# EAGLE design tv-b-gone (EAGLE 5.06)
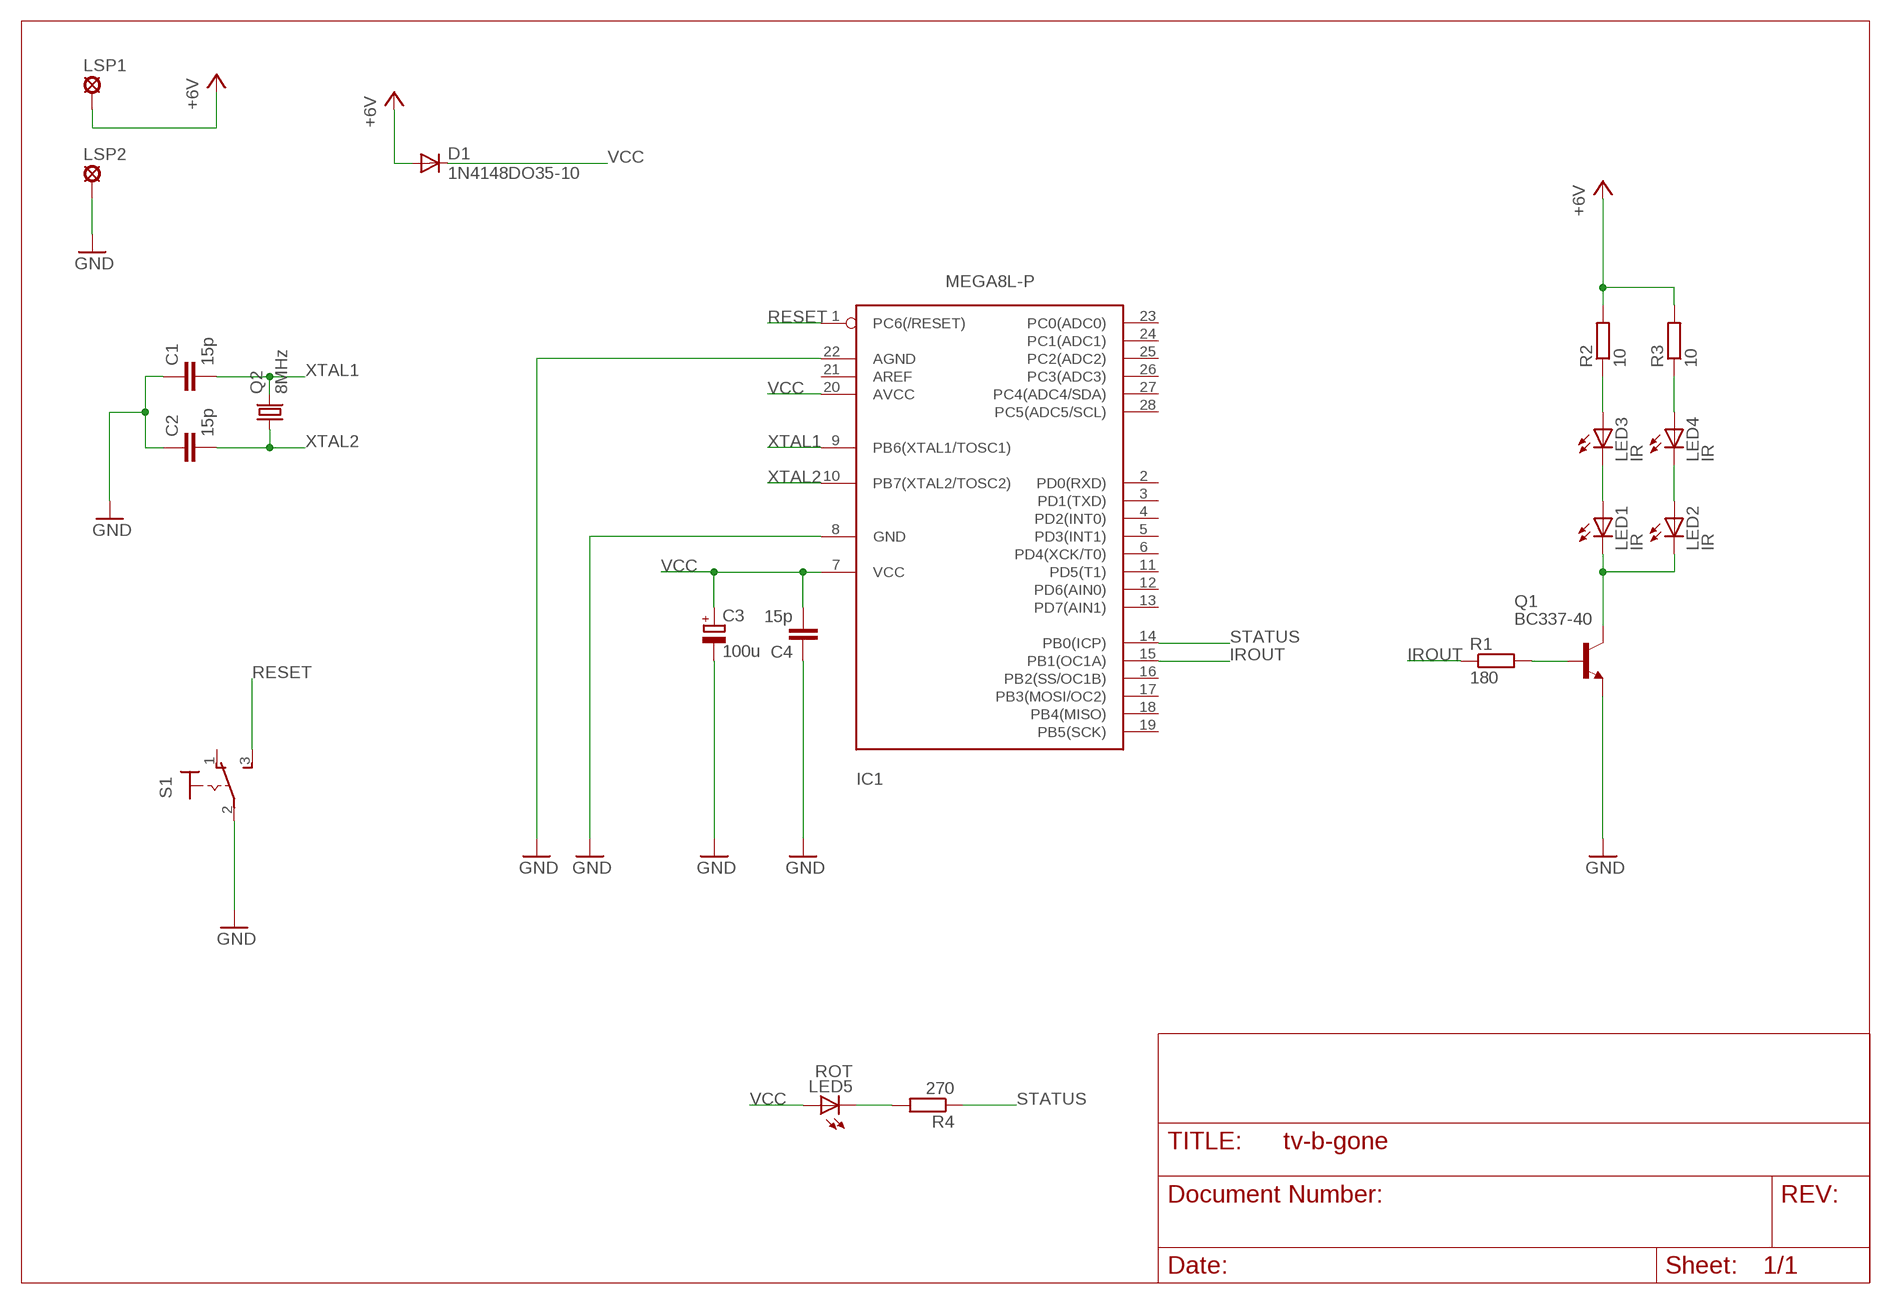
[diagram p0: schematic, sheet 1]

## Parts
C1  15p  C-EU025-030X050  [C025-030X050]
C2  15p  C-EU025-030X050  [C025-030X050]
C3  100u  CPOL-EUE2.5-5  [E2,5-5]
C4  15p  C-EU025-030X050  [C025-030X050]
D1  1N4148DO35-10  [DO35-10]
IC1  MEGA8L-P  MEGA8-P  [DIL28-3]
LED1  IR  LED5MM  [LED5MM]
LED2  IR  LED5MM  [LED5MM]
LED3  IR  LED5MM  [LED5MM]
LED4  IR  LED5MM  [LED5MM]
LED5  ROT  LED5MM  [LED5MM]
LSP1  SE14  [SE14]
LSP2  SE14  [SE14]
Q1  BC337-40  BC337  [TO92]
Q2  8MHz  CRYSTALHC49S  [HC49/S]
R1  180  R-EU_0309/12  [0309/12]
R2  10  R-EU_0309/12  [0309/12]
R3  10  R-EU_0309/12  [0309/12]
R4  270  R-EU_0309/12  [0309/12]
S1  M9040P  [M9040P]

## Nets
+5V: D1.A LSP1.MP R2.2 R3.2 ; supply symbol labelled +6V
GND: C1.1 C2.1 C3.- C4.1 IC1.8(GND) IC1.22(AGND) LSP2.MP Q1.1(E) S1.2(P)
IR-N$5: LED2.A LED4.K(C)
IROUT: IC1.15(PB1(OC1A)) R1.1
N$2: Q1.2(B) R1.2
N$3: LED1.K(C) LED2.K(C) Q1.3(C)
N$4: LED1.A LED3.K(C)
N$6: LED3.A R2.1
N$7: LED4.A R3.1
N$8: LED5.K(C) R4.2
RESET: IC1.1(PC6(/RESET)) S1.3(S)
STATUS: IC1.14(PB0(ICP)) R4.1
VCC: C3.+ C4.2 D1.C IC1.7(VCC) IC1.20(AVCC) LED5.A
XTAL1: C1.2 IC1.9(PB6(XTAL1/TOSC1)) Q2.2
XTAL2: C2.2 IC1.10(PB7(XTAL2/TOSC2)) Q2.1
Unconnected: IC1.2(PD0(RXD)) IC1.3(PD1(TXD)) IC1.4(PD2(INT0)) IC1.5(PD3(INT1)) IC1.6(PD4(XCK/T0)) IC1.11(PD5(T1)) IC1.12(PD6(AIN0)) IC1.13(PD7(AIN1)) IC1.16(PB2(SS/OC1B)) IC1.17(PB3(MOSI/OC2)) IC1.18(PB4(MISO)) IC1.19(PB5(SCK)) IC1.21(AREF) IC1.23(PC0(ADC0)) IC1.24(PC1(ADC1)) IC1.25(PC2(ADC2)) IC1.26(PC3(ADC3)) IC1.27(PC4(ADC4/SDA)) IC1.28(PC5(ADC5/SCL)) S1.1(O)

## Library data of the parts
C1 C2 C4 = rcl:C-EU: CAPACITOR, European symbol
C3 = rcl:CPOL-EU: POLARIZED CAPACITOR, European symbol
D1 = diode:1N4148: DIODE
IC1 = avr:MEGA8-P: MICROCONTROLLER 8 Kbytes FLASH 1 kbytes SRAM 512 bytes EEPROM USART 4-channel 10 bit ADC 2-channel 8 bit ADC
LED1-LED5 = led:LED: LED
LSP1 LSP2 = solpad:SE14: SOLDER PAD
Q1 = transistor-npn:BC337*: NPN Transistor
Q2 = crystal:CRYSTAL: CRYSTAL
R1-R4 = rcl:R-EU_: RESISTOR, European symbol
S1 = switch:M9040P: TOGGLE SWITCH Marquardt

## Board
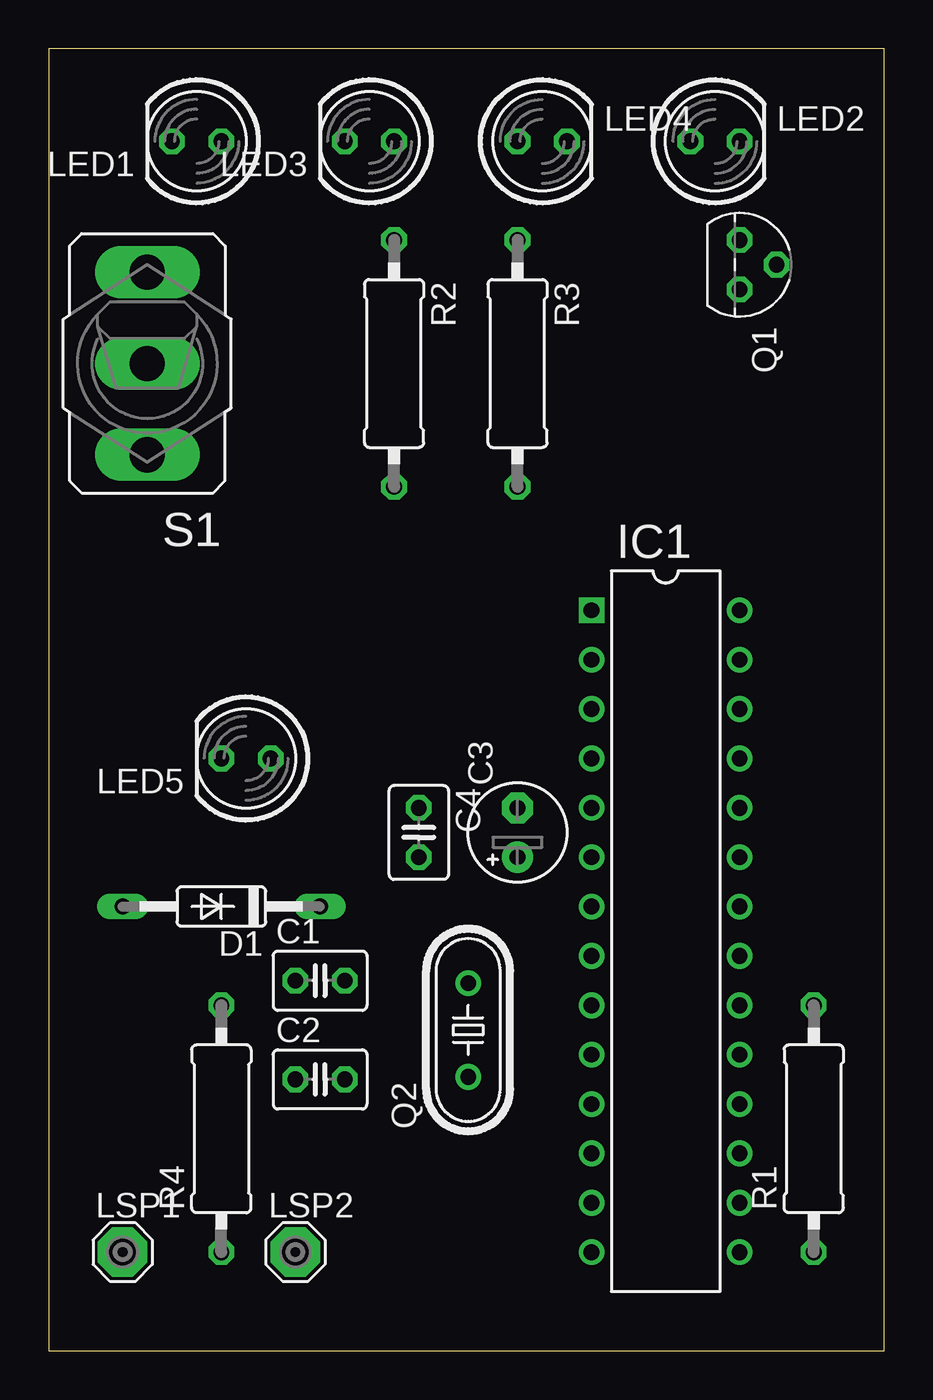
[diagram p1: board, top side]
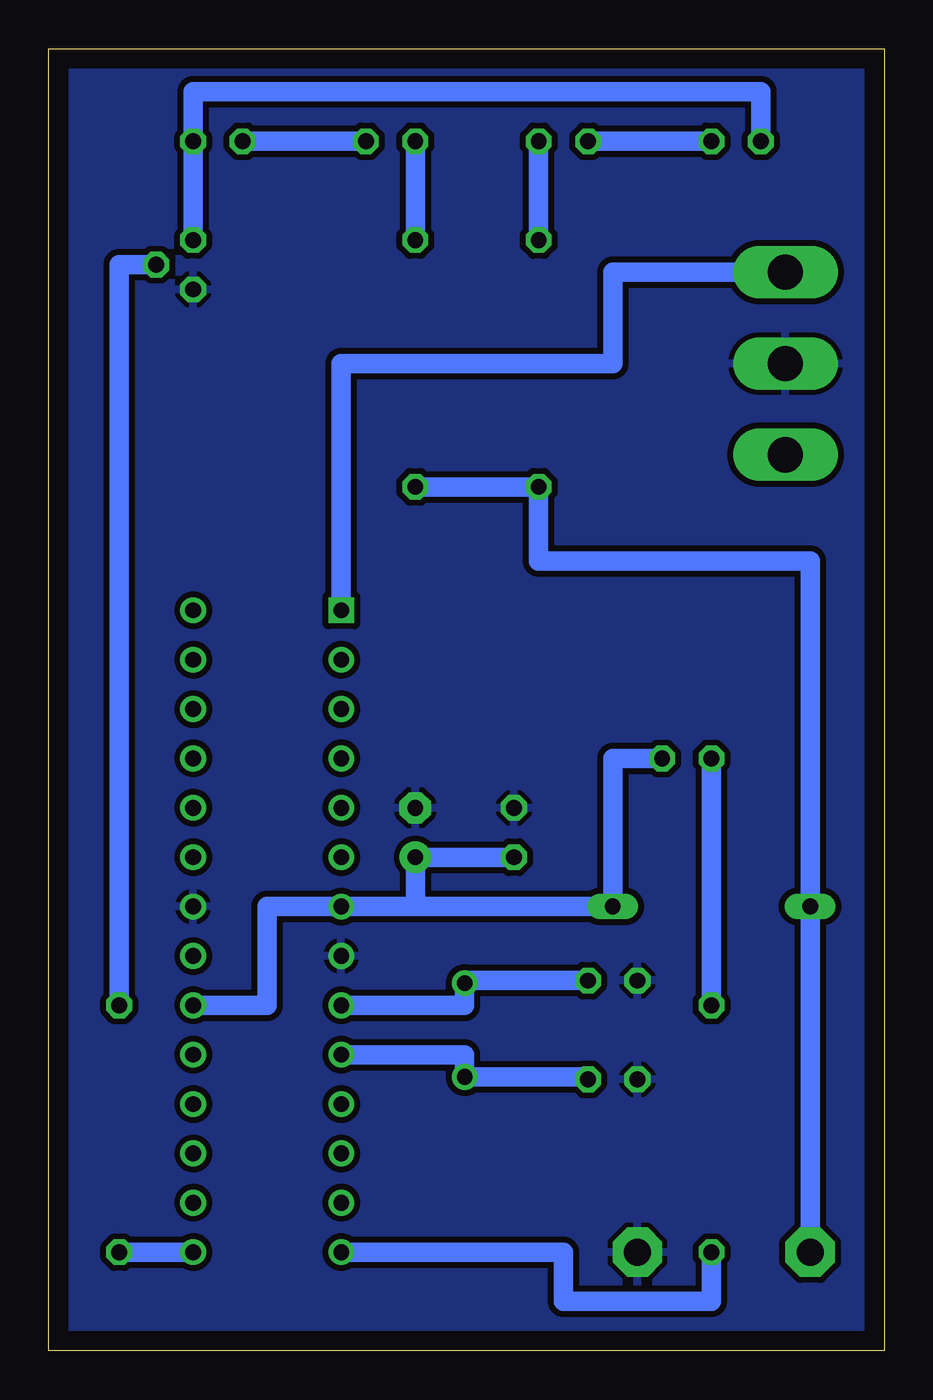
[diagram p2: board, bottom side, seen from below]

Size 43 x 67 mm. Coordinates in mm from the lower left corner, seen from the top.
Outline: 0,0 43,0 43,67 0,67 0,0
Copper layers (1*16): Top 0.035mm / dielectric 1.5mm / Bottom 0.035mm
Design rules "default *": minimum track width 10mil, minimum drill 24mil, track to track 12mil, track to pad 12mil, pad to pad 8mil, via to via 8mil, smd to smd 8mil, copper to edge 40mil, drill to drill 8mil, minimum pad ring 10mil, minimum via ring 8mil, stop-mask expansion 4mil, vias tented up to drill 0mil, thermal gap 10mil

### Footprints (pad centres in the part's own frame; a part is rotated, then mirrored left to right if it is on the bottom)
C025-030X050 = drill 0.813 octagon: 1 -1.27,0; 2 1.27,0
E2,5-5 = drill 0.813 pad 1.6 round: + -1.27,0 | drill 0.813 pad 1.6 octagon: - 1.27,0
DO35-10 = drill 0.813 long: A 5.08,0; C -5.08,0
DIL28-3 = drill 0.813 square: 1 -16.51,-3.81 | drill 0.813 round: 2 -13.97,-3.81; 3 -11.43,-3.81; 4 -8.89,-3.81; 5 -6.35,-3.81; 6 -3.81,-3.81; 7 -1.27,-3.81; 8 1.27,-3.81; 9 3.81,-3.81; 10 6.35,-3.81; 11 8.89,-3.81; 12 11.43,-3.81; 13 13.97,-3.81; 14 16.51,-3.81; 15 16.51,3.81; 16 13.97,3.81; 17 11.43,3.81; 18 8.89,3.81; 19 6.35,3.81; 20 3.81,3.81; 21 1.27,3.81; 22 -1.27,3.81; 23 -3.81,3.81; 24 -6.35,3.81; 25 -8.89,3.81; 26 -11.43,3.81; 27 -13.97,3.81; 28 -16.51,3.81
LED5MM = drill 0.813 octagon: A -1.27,0; K 1.27,0
SE14 = drill 1.397 pad 2.54 octagon: MP 0,0
TO92 = drill 0.813 octagon: 1 1.27,0; 2 0,1.905; 3 -1.27,0
HC49/S = drill 0.813 round: 1 -2.413,0; 2 2.413,0
0309/12 = drill 0.813 octagon: 1 -6.35,0; 2 6.35,0
M9040P = drill 1.803 long: 1 0,4.699; 2 0,0; 3 0,-4.699

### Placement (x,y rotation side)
C1  13.97,19.05 0 top
C2  13.97,13.97 0 top
C3  24.13,26.67 90 top
C4  19.05,26.67 270 top
D1  8.89,22.86 180 top
IC1  31.75,21.59 270 top
LED1  7.62,62.23 180 top
LED2  34.29,62.23 0 top
LED3  16.51,62.23 180 top
LED4  25.4,62.23 0 top
LED5  10.16,30.48 180 top
LSP1  3.81,5.08 0 top
LSP2  12.7,5.08 0 top
Q1  35.56,55.88 270 top
Q2  21.59,16.51 90 top
R1  39.37,11.43 90 top
R2  17.78,50.8 270 top
R3  24.13,50.8 270 top
R4  8.89,11.43 90 top
S1  5.08,50.8 180 top

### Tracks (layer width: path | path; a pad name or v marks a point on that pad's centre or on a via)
+5V
  Bottom 1: LSP1.MP D1.A 3.81,40.64 17.78,40.64 R2.2 R3.2
GND
  pour Bottom: -1.27,67.31 -1.27,-1.27 44.45,-1.27 44.45,68.58 -1.27,68.58
IR-N$5
  Bottom 1: LED4.K LED2.A
IROUT
  Bottom 1: IC1.15 R1.1
N$2
  Bottom 1: R1.2 39.37,55.88 Q1.2
N$3
  Bottom 1: Q1.3 LED2.K 35.56,64.77 6.35,64.77 LED1.K
N$4
  Bottom 1: LED1.A LED3.K
N$6
  Bottom 1: R2.1 LED3.A
N$7
  Bottom 1: R3.1 LED4.A
N$8
  Bottom 1: R4.2 LED5.K
RESET
  Bottom 1: S1.3 13.97,55.5 13.97,50.8 27.94,50.8 IC1.1
STATUS
  Bottom 1: R4.1 8.89,2.54 16.51,2.54 16.51,5.08 IC1.14
VCC
  Bottom 0.406: IC1.7 24.13,22.86
  Bottom 1: IC1.20 31.75,17.78 31.75,22.86 IC1.7 D1.C 13.97,30.48 LED5.A | 24.13,22.86 C3.+ C4.2
XTAL1
  Bottom 0.406: 21.59,19.05 Q2.2
  Bottom 1: IC1.9 21.59,17.78 Q2.2 | C1.2 21.59,19.05
XTAL2
  Bottom 0.406: C2.2 15.24,14.1
  Bottom 1: IC1.10 21.59,15.24 Q2.1 15.24,14.1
